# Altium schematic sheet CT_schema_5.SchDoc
size 274 x 160 mm
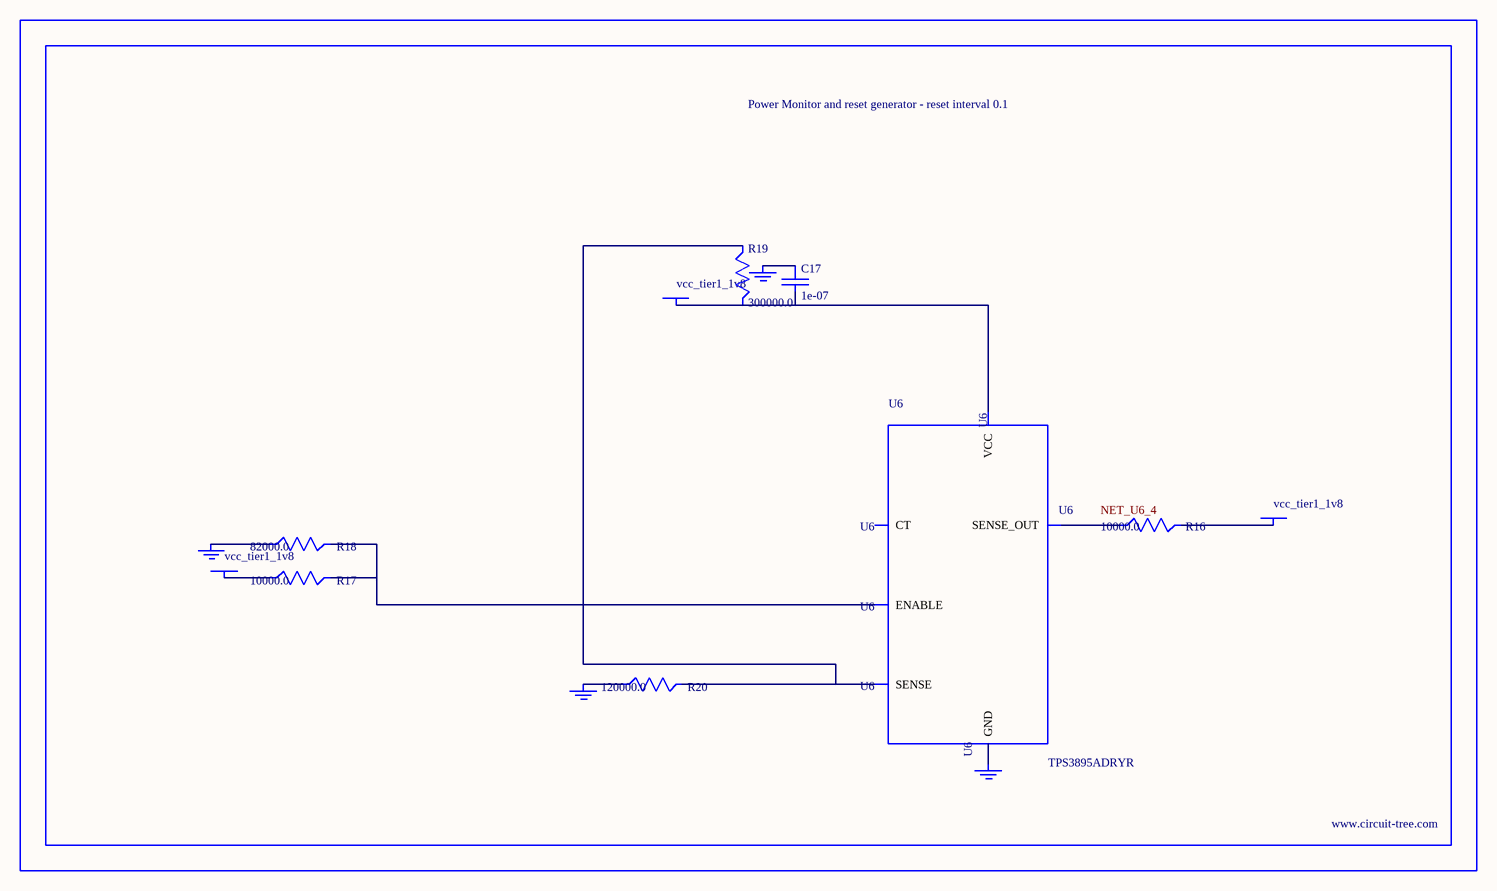
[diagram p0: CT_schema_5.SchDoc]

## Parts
BORDER4  (no value)
C17  1e-07  [C0402]
GND_INSTANCE_4_0  (no value)
GND_INSTANCE_4_1  (no value)
GND_INSTANCE_4_2  (no value)
GND_INSTANCE_4_3  (no value)
POWER_INSTANCE_4_0  vcc_tier1_1v8
POWER_INSTANCE_4_1  vcc_tier1_1v8
POWER_INSTANCE_4_2  vcc_tier1_1v8
R16  10000.0  [R0603]
R17  10000.0  [R0603]
R18  82000.0  [R0603]
R19  300000.0  [R0603]
R20  120000.0  [R0603]
U6  TPS3895ADRYR  [SON-6]

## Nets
NetC17_1: C17.1 GND_INSTANCE_4_2.0(GND)
NetC17_2: C17.2 POWER_INSTANCE_4_2.0(PWR) R19.2 U6.6(VCC)
NetGND_INSTANCE_4_0_0: GND_INSTANCE_4_0.0(GND) R18.1
NetGND_INSTANCE_4_1_0: GND_INSTANCE_4_1.0(GND) R20.1
NetGND_INSTANCE_4_3_0: GND_INSTANCE_4_3.0(GND) U6.2(GND)
NetPOWER_INSTANCE_4_0_0: POWER_INSTANCE_4_0.0(PWR) R17.1
NetPOWER_INSTANCE_4_1_0: POWER_INSTANCE_4_1.0(PWR) R16.2
NetR16_1: R16.1 U6.4(SENSE_OUT)
NetR17_2: R17.2 R18.2 U6.1(ENABLE)
NetR19_1: R19.1 R20.2 U6.3(SENSE)

Not connected (* = marked no-connect by the designer): U6 5(CT)

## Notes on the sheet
- Labels drawn without touching a wire or pin: NET_U6_4

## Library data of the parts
BORDER4 = BORDER_PAGE4
C17 = C0402C104K3RACTU
GND_INSTANCE_4_0-GND_INSTANCE_4_3 = GND
POWER_INSTANCE_4_0-POWER_INSTANCE_4_2 = PWR
R16 R17 = RC0603JR-0710KL
R18 = RC0603JR-0782KL
R19 = RC0603JR-07300KL
R20 = RC0603JR-07120KL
